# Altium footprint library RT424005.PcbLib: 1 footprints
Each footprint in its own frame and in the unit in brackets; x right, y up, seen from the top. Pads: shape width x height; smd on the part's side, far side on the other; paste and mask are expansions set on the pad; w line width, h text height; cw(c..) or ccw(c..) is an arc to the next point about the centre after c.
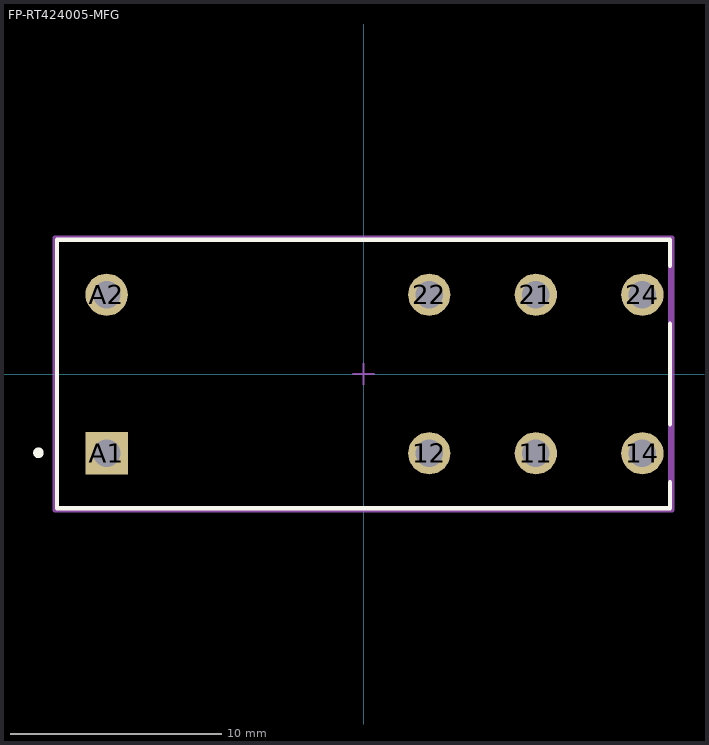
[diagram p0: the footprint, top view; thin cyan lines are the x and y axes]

## FP-RT424005-MFG [mm]
pads (8):
  round 2 hole 1.3 paste-2539.97 mask+0: 11(8.15,-3.75) 12(3.11,-3.75) 14(13.19,-3.75) 21(8.15,3.75) 22(3.11,3.75) 24(13.19,3.75) A2(-12.15,3.75)
  rect 2x2 hole 1.3 paste-2539.97 mask+0: A1(-12.15,-3.75)
Top Overlay:
  circle w0.25: c-15.375,-3.725 r0.125
  lines w0.2: 14.5,-5.125 14.5,-6.35 -14.5,-6.35 -14.5,6.35 14.5,6.35 14.5,5.125 ; 14.5,-2.375 14.5,2.375
Top Assembly:
  lines w0.2: -14.6,-6.45 -14.6,6.45 14.6,6.45 14.6,-6.45 -14.6,-6.45
  text ".Designator" at 0,0.188 h1
Top 3D Body:
  lines w0.2: -14.5,-6.35 -14.5,6.35 14.5,6.35 14.5,-6.35 -14.5,-6.35
Top Courtyard:
  lines w0.2: -14.6,-6.45 -14.6,6.45 14.6,6.45 14.6,-6.45 -14.6,-6.45
Top Component Center:
  lines w0.1: -0.5,0 0.5,0 ; 0,-0.5 0,0.5
3D body "Relay_TE_Connectivity_RT424005_eec.STEP": height 0.25, standoff 0, extent -14.6,-6.45 14.6,6.45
